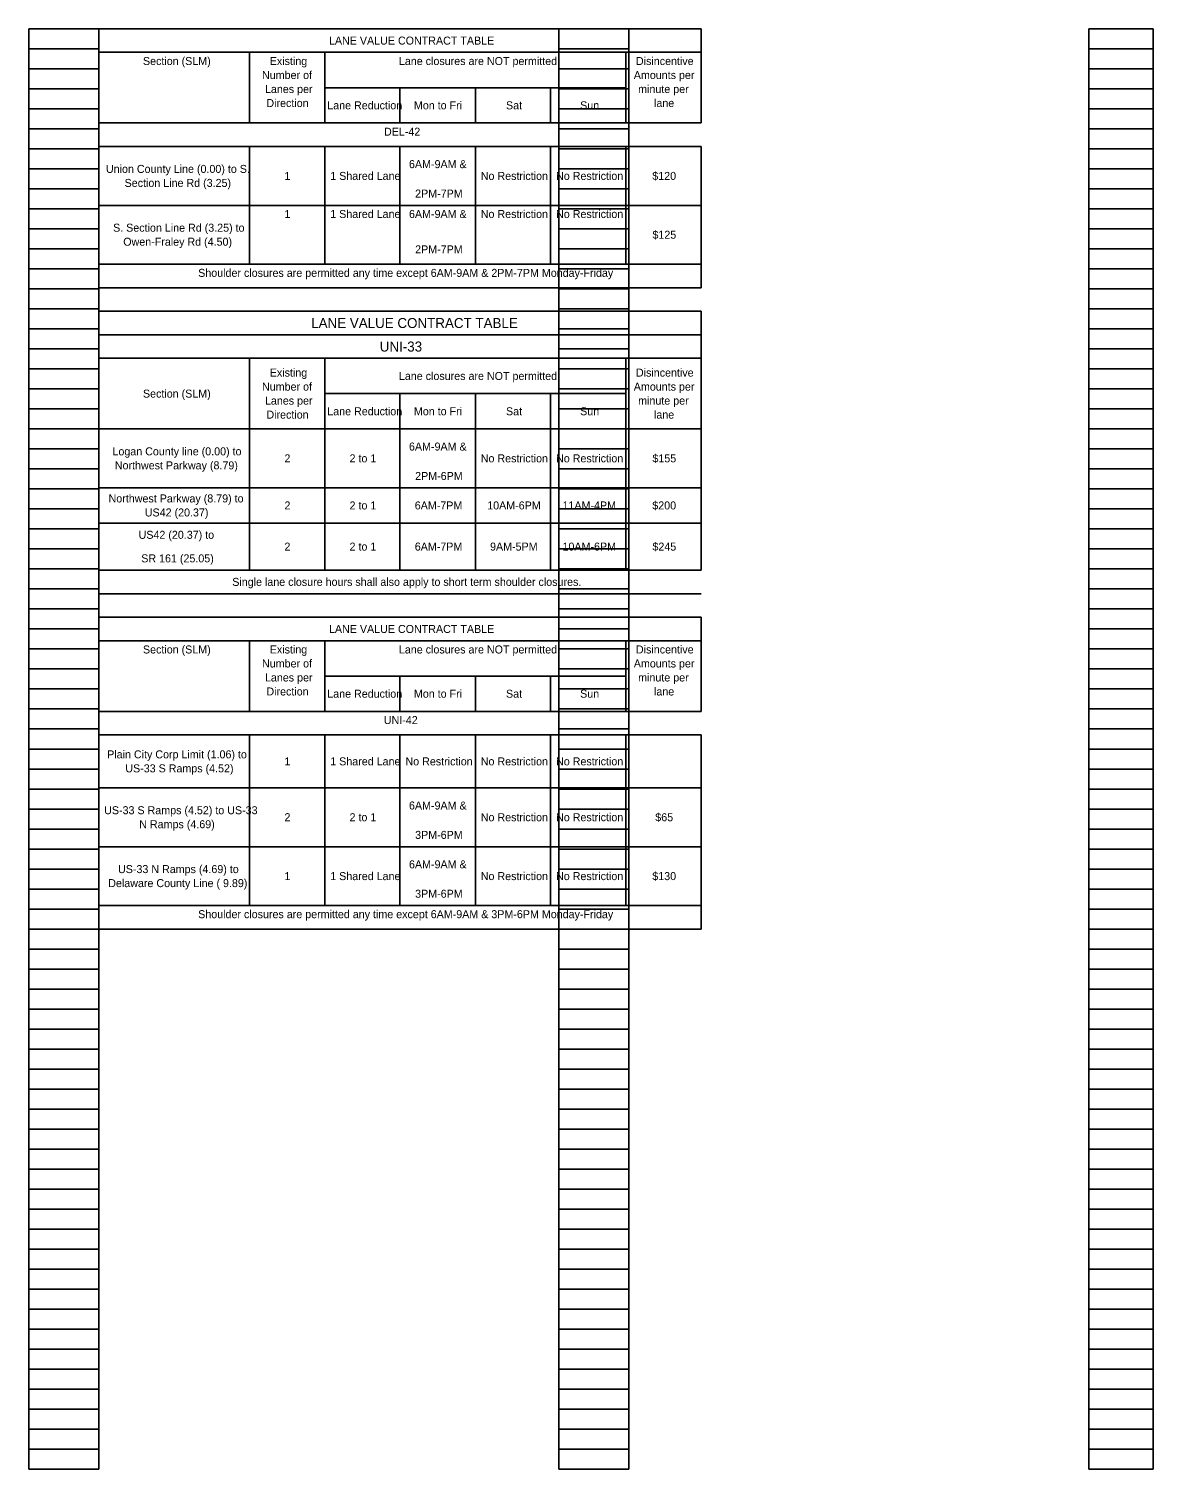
# Model space of a CAD drawing. Extents: x 0 to 32, y -44 to 21.1.
# Drawn here: x 16.26 to 32, y -43.02 to -22.86 of the extents above; entities that cross this region are included whole.
import ezdxf

# ---------------------------------------------------------------- set-up
doc = ezdxf.new("R2010")
doc.units = 0
doc.layers.add('SH_Data', color=7, linetype='Continuous')
doc.layers.add('SH_Text', color=7, linetype='Continuous')

msp = doc.modelspace()

# ---------------------------------------------------------------- linework, layer by layer
at = {"layer": 'SH_Data'}
for p, q in [((16.26, -43.02), (16.26, -22.86)), ((16.26, -22.86), (17.24, -22.86)), ((17.24, -43.02), (17.24, -22.86)), ((17.24, -22.86), (25.673, -22.86)), ((17.24, -22.86), (17.24, -26.484)), ((23.68, -43.02), (23.68, -22.86)), ((23.68, -22.86), (24.66, -22.86)), ((24.66, -43.02), (24.66, -22.86)), ((25.673, -22.86), (25.673, -24.178)), ((31.1, -43.02), (31.1, -22.86)), ((31.1, -22.86), (32, -22.86)), ((32, -43.02), (32, -22.86)), ((16.26, -23.14), (17.24, -23.14)), ((23.68, -23.14), (24.66, -23.14)), ((31.1, -23.14), (32, -23.14)), ((17.24, -23.189), (25.673, -23.189)), ((19.348, -23.189), (19.348, -24.178)), ((20.402, -23.189), (20.402, -24.178)), ((24.619, -23.189), (24.619, -24.178)), ((16.26, -23.42), (17.24, -23.42)), ((23.68, -23.42), (24.66, -23.42)), ((31.1, -23.42), (32, -23.42)), ((16.26, -23.7), (17.24, -23.7)), ((20.402, -23.684), (24.619, -23.684)), ((21.456, -23.684), (21.456, -24.178)), ((22.511, -23.684), (22.511, -24.178)), ((23.565, -23.684), (23.565, -24.178)), ((23.68, -23.7), (24.66, -23.7)), ((31.1, -23.7), (32, -23.7)), ((16.26, -23.98), (17.24, -23.98)), ((23.68, -23.98), (24.66, -23.98)), ((31.1, -23.98), (32, -23.98)), ((17.24, -24.178), (25.673, -24.178)), ((16.26, -24.26), (17.24, -24.26)), ((23.68, -24.26), (24.66, -24.26)), ((31.1, -24.26), (32, -24.26)), ((16.26, -24.54), (17.24, -24.54)), ((17.24, -24.507), (25.673, -24.507)), ((19.348, -24.507), (19.348, -26.154)), ((20.402, -24.507), (20.402, -26.154)), ((21.456, -24.507), (21.456, -26.154)), ((22.511, -24.507), (22.511, -26.154)), ((23.565, -24.507), (23.565, -26.154)), ((23.68, -24.54), (24.66, -24.54)), ((24.619, -24.507), (24.619, -26.154)), ((25.673, -24.507), (25.673, -26.484)), ((31.1, -24.54), (32, -24.54)), ((16.26, -24.82), (17.24, -24.82)), ((23.68, -24.82), (24.66, -24.82)), ((31.1, -24.82), (32, -24.82)), ((16.26, -25.1), (17.24, -25.1)), ((23.68, -25.1), (24.66, -25.1)), ((31.1, -25.1), (32, -25.1)), ((16.26, -25.38), (17.24, -25.38)), ((17.24, -25.331), (25.673, -25.331)), ((23.68, -25.38), (24.66, -25.38)), ((31.1, -25.38), (32, -25.38)), ((16.26, -25.66), (17.24, -25.66)), ((23.68, -25.66), (24.66, -25.66)), ((31.1, -25.66), (32, -25.66)), ((16.26, -25.94), (17.24, -25.94)), ((23.68, -25.94), (24.66, -25.94)), ((31.1, -25.94), (32, -25.94)), ((17.24, -26.154), (25.673, -26.154)), ((16.26, -26.22), (17.24, -26.22)), ((23.68, -26.22), (24.66, -26.22)), ((31.1, -26.22), (32, -26.22)), ((16.26, -26.5), (17.24, -26.5)), ((17.24, -26.484), (25.673, -26.484)), ((23.68, -26.5), (24.66, -26.5)), ((31.1, -26.5), (32, -26.5)), ((16.26, -26.78), (17.24, -26.78)), ((23.68, -26.78), (24.66, -26.78)), ((31.1, -26.78), (32, -26.78)), ((17.24, -26.813), (25.673, -26.813)), ((17.24, -26.813), (17.24, -30.766)), ((25.673, -26.813), (25.673, -30.436)), ((16.26, -27.06), (17.24, -27.06)), ((17.24, -27.142), (25.673, -27.142)), ((23.68, -27.06), (24.66, -27.06)), ((31.1, -27.06), (32, -27.06)), ((16.26, -27.34), (17.24, -27.34)), ((23.68, -27.34), (24.66, -27.34)), ((31.1, -27.34), (32, -27.34)), ((17.24, -27.472), (25.673, -27.472)), ((19.348, -27.472), (19.348, -30.436)), ((20.402, -27.472), (20.402, -30.436)), ((24.619, -27.472), (24.619, -30.436)), ((16.26, -27.62), (17.24, -27.62)), ((23.68, -27.62), (24.66, -27.62)), ((31.1, -27.62), (32, -27.62)), ((16.26, -27.9), (17.24, -27.9)), ((20.402, -27.966), (24.619, -27.966)), ((21.456, -27.966), (21.456, -30.436)), ((22.511, -27.966), (22.511, -30.436)), ((23.565, -27.966), (23.565, -30.436)), ((23.68, -27.9), (24.66, -27.9)), ((31.1, -27.9), (32, -27.9)), ((16.26, -28.18), (17.24, -28.18)), ((23.68, -28.18), (24.66, -28.18)), ((31.1, -28.18), (32, -28.18)), ((16.26, -28.46), (17.24, -28.46)), ((17.24, -28.46), (25.673, -28.46)), ((23.68, -28.46), (24.66, -28.46)), ((31.1, -28.46), (32, -28.46)), ((16.26, -28.74), (17.24, -28.74)), ((23.68, -28.74), (24.66, -28.74)), ((31.1, -28.74), (32, -28.74)), ((16.26, -29.02), (17.24, -29.02)), ((23.68, -29.02), (24.66, -29.02)), ((31.1, -29.02), (32, -29.02)), ((16.26, -29.3), (17.24, -29.3)), ((17.24, -29.284), (25.673, -29.284)), ((23.68, -29.3), (24.66, -29.3)), ((31.1, -29.3), (32, -29.3)), ((16.26, -29.58), (17.24, -29.58)), ((23.68, -29.58), (24.66, -29.58)), ((31.1, -29.58), (32, -29.58)), ((17.24, -29.778), (25.673, -29.778)), ((16.26, -29.86), (17.24, -29.86)), ((23.68, -29.86), (24.66, -29.86)), ((31.1, -29.86), (32, -29.86)), ((16.26, -30.14), (17.24, -30.14)), ((23.68, -30.14), (24.66, -30.14)), ((31.1, -30.14), (32, -30.14)), ((16.26, -30.42), (17.24, -30.42)), ((17.24, -30.436), (25.673, -30.436)), ((23.68, -30.42), (24.66, -30.42)), ((31.1, -30.42), (32, -30.42)), ((16.26, -30.7), (17.24, -30.7)), ((17.24, -30.766), (25.673, -30.766)), ((23.68, -30.7), (24.66, -30.7)), ((31.1, -30.7), (32, -30.7)), ((16.26, -30.98), (17.24, -30.98)), ((23.68, -30.98), (24.66, -30.98)), ((31.1, -30.98), (32, -30.98)), ((17.24, -31.095), (25.673, -31.095)), ((17.24, -31.095), (17.24, -35.46)), ((25.673, -31.095), (25.673, -32.413)), ((16.26, -31.26), (17.24, -31.26)), ((17.24, -31.425), (25.673, -31.425)), ((19.348, -31.425), (19.348, -32.413)), ((20.402, -31.425), (20.402, -32.413)), ((23.68, -31.26), (24.66, -31.26)), ((24.619, -31.425), (24.619, -32.413)), ((31.1, -31.26), (32, -31.26)), ((16.26, -31.54), (17.24, -31.54)), ((23.68, -31.54), (24.66, -31.54)), ((31.1, -31.54), (32, -31.54)), ((16.26, -31.82), (17.24, -31.82)), ((23.68, -31.82), (24.66, -31.82)), ((31.1, -31.82), (32, -31.82)), ((20.402, -31.919), (24.619, -31.919)), ((21.456, -31.919), (21.456, -32.413)), ((22.511, -31.919), (22.511, -32.413)), ((23.565, -31.919), (23.565, -32.413)), ((16.26, -32.1), (17.24, -32.1)), ((23.68, -32.1), (24.66, -32.1)), ((31.1, -32.1), (32, -32.1)), ((16.26, -32.38), (17.24, -32.38)), ((17.24, -32.413), (25.673, -32.413)), ((23.68, -32.38), (24.66, -32.38)), ((31.1, -32.38), (32, -32.38)), ((16.26, -32.66), (17.24, -32.66)), ((17.24, -32.742), (25.673, -32.742)), ((19.348, -32.742), (19.348, -35.131)), ((20.402, -32.742), (20.402, -35.131)), ((21.456, -32.742), (21.456, -35.131)), ((22.511, -32.742), (22.511, -35.131)), ((23.565, -32.742), (23.565, -35.131)), ((23.68, -32.66), (24.66, -32.66)), ((24.619, -32.742), (24.619, -35.131)), ((25.673, -32.742), (25.673, -35.46)), ((31.1, -32.66), (32, -32.66)), ((16.26, -32.94), (17.24, -32.94)), ((23.68, -32.94), (24.66, -32.94)), ((31.1, -32.94), (32, -32.94)), ((16.26, -33.22), (17.24, -33.22)), ((23.68, -33.22), (24.66, -33.22)), ((31.1, -33.22), (32, -33.22)), ((16.26, -33.5), (17.24, -33.5)), ((17.24, -33.484), (25.673, -33.484)), ((23.68, -33.5), (24.66, -33.5)), ((31.1, -33.5), (32, -33.5)), ((16.26, -33.78), (17.24, -33.78)), ((23.68, -33.78), (24.66, -33.78)), ((31.1, -33.78), (32, -33.78)), ((16.26, -34.06), (17.24, -34.06)), ((23.68, -34.06), (24.66, -34.06)), ((31.1, -34.06), (32, -34.06)), ((16.26, -34.34), (17.24, -34.34)), ((17.24, -34.307), (25.673, -34.307)), ((23.68, -34.34), (24.66, -34.34)), ((31.1, -34.34), (32, -34.34)), ((16.26, -34.62), (17.24, -34.62)), ((23.68, -34.62), (24.66, -34.62)), ((31.1, -34.62), (32, -34.62)), ((16.26, -34.9), (17.24, -34.9)), ((23.68, -34.9), (24.66, -34.9)), ((31.1, -34.9), (32, -34.9)), ((16.26, -35.18), (17.24, -35.18)), ((17.24, -35.131), (25.673, -35.131)), ((23.68, -35.18), (24.66, -35.18)), ((31.1, -35.18), (32, -35.18)), ((16.26, -35.46), (17.24, -35.46)), ((17.24, -35.46), (25.673, -35.46)), ((23.68, -35.46), (24.66, -35.46)), ((31.1, -35.46), (32, -35.46)), ((16.26, -35.74), (17.24, -35.74)), ((23.68, -35.74), (24.66, -35.74)), ((31.1, -35.74), (32, -35.74)), ((16.26, -36.02), (17.24, -36.02)), ((23.68, -36.02), (24.66, -36.02)), ((31.1, -36.02), (32, -36.02)), ((16.26, -36.3), (17.24, -36.3)), ((23.68, -36.3), (24.66, -36.3)), ((31.1, -36.3), (32, -36.3)), ((16.26, -36.58), (17.24, -36.58)), ((23.68, -36.58), (24.66, -36.58)), ((31.1, -36.58), (32, -36.58)), ((16.26, -36.86), (17.24, -36.86)), ((23.68, -36.86), (24.66, -36.86)), ((31.1, -36.86), (32, -36.86)), ((16.26, -37.14), (17.24, -37.14)), ((23.68, -37.14), (24.66, -37.14)), ((31.1, -37.14), (32, -37.14)), ((16.26, -37.42), (17.24, -37.42)), ((23.68, -37.42), (24.66, -37.42)), ((31.1, -37.42), (32, -37.42)), ((16.26, -37.7), (17.24, -37.7)), ((23.68, -37.7), (24.66, -37.7)), ((31.1, -37.7), (32, -37.7)), ((16.26, -37.98), (17.24, -37.98)), ((23.68, -37.98), (24.66, -37.98)), ((31.1, -37.98), (32, -37.98)), ((16.26, -38.26), (17.24, -38.26)), ((23.68, -38.26), (24.66, -38.26)), ((31.1, -38.26), (32, -38.26)), ((16.26, -38.54), (17.24, -38.54)), ((23.68, -38.54), (24.66, -38.54)), ((31.1, -38.54), (32, -38.54)), ((16.26, -38.82), (17.24, -38.82)), ((23.68, -38.82), (24.66, -38.82)), ((31.1, -38.82), (32, -38.82)), ((16.26, -39.1), (17.24, -39.1)), ((23.68, -39.1), (24.66, -39.1)), ((31.1, -39.1), (32, -39.1)), ((16.26, -39.38), (17.24, -39.38)), ((23.68, -39.38), (24.66, -39.38)), ((31.1, -39.38), (32, -39.38)), ((16.26, -39.66), (17.24, -39.66)), ((23.68, -39.66), (24.66, -39.66)), ((31.1, -39.66), (32, -39.66)), ((16.26, -39.94), (17.24, -39.94)), ((23.68, -39.94), (24.66, -39.94)), ((31.1, -39.94), (32, -39.94)), ((16.26, -40.22), (17.24, -40.22)), ((23.68, -40.22), (24.66, -40.22)), ((31.1, -40.22), (32, -40.22)), ((16.26, -40.5), (17.24, -40.5)), ((23.68, -40.5), (24.66, -40.5)), ((31.1, -40.5), (32, -40.5)), ((16.26, -40.78), (17.24, -40.78)), ((23.68, -40.78), (24.66, -40.78)), ((31.1, -40.78), (32, -40.78)), ((16.26, -41.06), (17.24, -41.06)), ((23.68, -41.06), (24.66, -41.06)), ((31.1, -41.06), (32, -41.06)), ((16.26, -41.34), (17.24, -41.34)), ((23.68, -41.34), (24.66, -41.34)), ((31.1, -41.34), (32, -41.34)), ((16.26, -41.62), (17.24, -41.62)), ((23.68, -41.62), (24.66, -41.62)), ((31.1, -41.62), (32, -41.62)), ((16.26, -41.9), (17.24, -41.9)), ((23.68, -41.9), (24.66, -41.9)), ((31.1, -41.9), (32, -41.9)), ((16.26, -42.18), (17.24, -42.18)), ((23.68, -42.18), (24.66, -42.18)), ((31.1, -42.18), (32, -42.18)), ((16.26, -42.46), (17.24, -42.46)), ((23.68, -42.46), (24.66, -42.46)), ((31.1, -42.46), (32, -42.46)), ((16.26, -42.74), (17.24, -42.74)), ((23.68, -42.74), (24.66, -42.74)), ((31.1, -42.74), (32, -42.74)), ((16.26, -43.02), (17.24, -43.02)), ((23.68, -43.02), (24.66, -43.02)), ((31.1, -43.02), (32, -43.02))]:
    msp.add_line(p, q, dxfattribs=at)

# ---------------------------------------------------------------- texts
at = {"layer": 'SH_Text'}
for s, height, p in [('LANE VALUE CONTRACT TABLE', 0.112, (20.462, -23.081)), ('Section (SLM)', 0.112, (17.858, -23.367)), ('Existing ', 0.112, (19.633, -23.367)), ('Lane closures are NOT permitted:', 0.112, (21.441, -23.367)), ('Disincentive ', 0.112, (24.759, -23.367)), ('Number of ', 0.112, (19.525, -23.563)), ('Amounts per ', 0.112, (24.729, -23.563)), ('Lanes per ', 0.112, (19.566, -23.759)), ('minute per ', 0.112, (24.79, -23.759)), ('Direction', 0.112, (19.586, -23.955)), ('Lane Reduction', 0.112, (20.438, -23.987)), ('Mon to Fri', 0.112, (21.651, -23.987)), ('Sat', 0.112, (22.94, -23.987)), ('Sun', 0.112, (23.978, -23.987)), ('lane', 0.112, (25.012, -23.955)), ('DEL-42', 0.112, (21.232, -24.356)), ('Union County Line (0.00) to S. ', 0.112, (17.34, -24.877)), ('6AM-9AM &', 0.112, (21.582, -24.81)), ('Section Line Rd (3.25)', 0.112, (17.601, -25.073)), ('1', 0.112, (19.839, -24.975)), ('1 Shared Lane', 0.112, (20.48, -24.975)), ('No Restriction', 0.112, (22.587, -24.975)), ('No Restriction', 0.112, (23.641, -24.975)), ('$120', 0.112, (24.988, -24.975)), ('2PM-7PM', 0.112, (21.668, -25.222)), ('1', 0.112, (19.839, -25.508)), ('1 Shared Lane', 0.112, (20.48, -25.508)), ('6AM-9AM &', 0.112, (21.582, -25.508)), ('No Restriction', 0.112, (22.587, -25.508)), ('No Restriction', 0.112, (23.641, -25.508)), ('S. Section Line Rd (3.25) to ', 0.112, (17.44, -25.7)), ('Owen-Fraley Rd (4.50)', 0.112, (17.582, -25.896)), ('$125', 0.112, (24.99, -25.798)), ('2PM-7PM', 0.112, (21.668, -26.003)), ('Shoulder closures are permitted any time except 6AM-9AM & 2PM-7PM Monday-Friday', 0.112, (18.631, -26.332)), ('LANE VALUE CONTRACT TABLE', 0.14, (20.213, -27.048)), ('UNI-33', 0.14, (21.173, -27.377)), ('Existing ', 0.112, (19.633, -27.728)), ('Disincentive ', 0.112, (24.759, -27.728)), ('Number of ', 0.112, (19.525, -27.924)), ('Lane closures are NOT permitted:', 0.112, (21.441, -27.775)), ('Amounts per ', 0.112, (24.729, -27.924)), ('Section (SLM)', 0.112, (17.858, -28.022)), ('Lanes per ', 0.112, (19.566, -28.12)), ('minute per ', 0.112, (24.79, -28.12)), ('Direction', 0.112, (19.586, -28.316)), ('Lane Reduction', 0.112, (20.438, -28.269)), ('Mon to Fri', 0.112, (21.651, -28.269)), ('Sat', 0.112, (22.94, -28.269)), ('Sun', 0.112, (23.978, -28.269)), ('lane', 0.112, (25.012, -28.316)), ('Logan County line (0.00) to ', 0.112, (17.431, -28.83)), ('2', 0.112, (19.839, -28.928)), ('2 to 1', 0.112, (20.75, -28.928)), ('6AM-9AM &', 0.112, (21.582, -28.763)), ('No Restriction', 0.112, (22.587, -28.928)), ('No Restriction', 0.112, (23.641, -28.928)), ('$155', 0.112, (24.99, -28.928)), ('Northwest Parkway (8.79)', 0.112, (17.464, -29.026)), ('2PM-6PM', 0.112, (21.668, -29.175)), ('Northwest Parkway (8.79) to ', 0.112, (17.377, -29.489)), ('US42 (20.37)', 0.112, (17.884, -29.685)), ('2', 0.112, (19.839, -29.587)), ('2 to 1', 0.112, (20.75, -29.587)), ('6AM-7PM', 0.112, (21.663, -29.587)), ('10AM-6PM', 0.112, (22.677, -29.587)), ('11AM-4PM', 0.112, (23.731, -29.587)), ('$200', 0.112, (24.988, -29.587)), ('US42 (20.37) to', 0.112, (17.797, -29.998)), ('SR 161 (25.05)', 0.112, (17.834, -30.328)), ('2', 0.112, (19.839, -30.163)), ('2 to 1', 0.112, (20.75, -30.163)), ('6AM-7PM', 0.112, (21.663, -30.163)), ('9AM-5PM', 0.112, (22.717, -30.163)), ('10AM-6PM', 0.112, (23.731, -30.163)), ('$245', 0.112, (24.99, -30.163)), ('Single lane closure hours shall also apply to short term shoulder closures.', 0.112, (19.108, -30.657)), ('LANE VALUE CONTRACT TABLE', 0.112, (20.462, -31.316)), ('Section (SLM)', 0.112, (17.858, -31.603)), ('Existing ', 0.112, (19.633, -31.603)), ('Lane closures are NOT permitted:', 0.112, (21.441, -31.603)), ('Disincentive ', 0.112, (24.759, -31.603)), ('Number of ', 0.112, (19.525, -31.799)), ('Amounts per ', 0.112, (24.729, -31.799)), ('Lanes per ', 0.112, (19.566, -31.995)), ('minute per ', 0.112, (24.79, -31.995)), ('Direction', 0.112, (19.586, -32.191)), ('Lane Reduction', 0.112, (20.438, -32.222)), ('Mon to Fri', 0.112, (21.651, -32.222)), ('Sat', 0.112, (22.94, -32.222)), ('Sun', 0.112, (23.978, -32.222)), ('lane', 0.112, (25.012, -32.191)), ('UNI-42', 0.112, (21.23, -32.591)), ('Plain City Corp Limit (1.06) to ', 0.112, (17.357, -33.071)), ('1', 0.112, (19.839, -33.169)), ('1 Shared Lane', 0.112, (20.48, -33.169)), ('No Restriction', 0.112, (21.533, -33.169)), ('No Restriction', 0.112, (22.587, -33.169)), ('No Restriction', 0.112, (23.641, -33.169)), ('US-33 S Ramps (4.52)', 0.112, (17.611, -33.267)), ('US-33 S Ramps (4.52) to US-33 ', 0.112, (17.315, -33.853)), ('2', 0.112, (19.839, -33.951)), ('2 to 1', 0.112, (20.75, -33.951)), ('6AM-9AM &', 0.112, (21.582, -33.787)), ('No Restriction', 0.112, (22.587, -33.951)), ('No Restriction', 0.112, (23.641, -33.951)), ('$65', 0.112, (25.03, -33.951)), ('N Ramps (4.69)', 0.112, (17.806, -34.049)), ('3PM-6PM', 0.112, (21.668, -34.198)), ('US-33 N Ramps (4.69) to ', 0.112, (17.509, -34.677)), ('1', 0.112, (19.839, -34.775)), ('1 Shared Lane', 0.112, (20.48, -34.775)), ('6AM-9AM &', 0.112, (21.582, -34.61)), ('No Restriction', 0.112, (22.587, -34.775)), ('No Restriction', 0.112, (23.641, -34.775)), ('$130', 0.112, (24.988, -34.775)), ('Delaware County Line ( 9.89)', 0.112, (17.372, -34.873)), ('3PM-6PM', 0.112, (21.668, -35.022)), ('Shoulder closures are permitted any time except 6AM-9AM & 3PM-6PM Monday-Friday', 0.112, (18.631, -35.308))]:
    msp.add_text(s, height=height, dxfattribs=at).set_placement(p)

doc.saveas('drawing.dxf')
